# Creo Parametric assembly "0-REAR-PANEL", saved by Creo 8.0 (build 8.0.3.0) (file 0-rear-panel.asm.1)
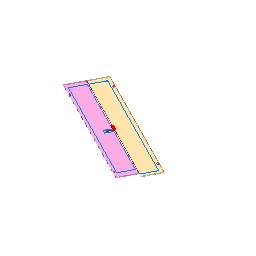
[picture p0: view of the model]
Units: millimeter Newton Second (mmNs); MM, TONNE, SECS

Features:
  1. datum plane "ADTM1"
  2. datum plane "ADTM2"
  3. datum plane "ADTM3"
  4. coordinate system
  5. component "1_MASTER-DOOR"
  6. component "2_POLE-COVER"
  7. component "1_ASSISTANT-DOOR"
  8. component "2_POLE-COVER"
  9. component "2_RUBBER"
  10. component "2_RUBBER"
  11. component "2_RUBBER"
  12. component "2_RUBBER"
  13. component "2_RUBBER"
  14. component "1_POLE"
  15. component "1_POLE"
  16. component "1_FIXER"
  17. component "1_FIXER"
  18. component "1_FIXER"
  19. component "1_FIXER"
  20. component "1_DOOR-SPINDLE"
  21. component "1_DOOR-SPINDLE"
  22. component "1_DOOR-SPINDLE"
  23. component "1_DOOR-SPINDLE"
  24. component "4_REAR_LOCK"
  25. component "4_LOCK"

Other named items: COPIED_GROUP, COPIED_GROUP_1, COPIED_GROUP_2, COPIED_GROUP_3, COPIED_GROUP_4, ACS0, VIS0001, VIS0002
